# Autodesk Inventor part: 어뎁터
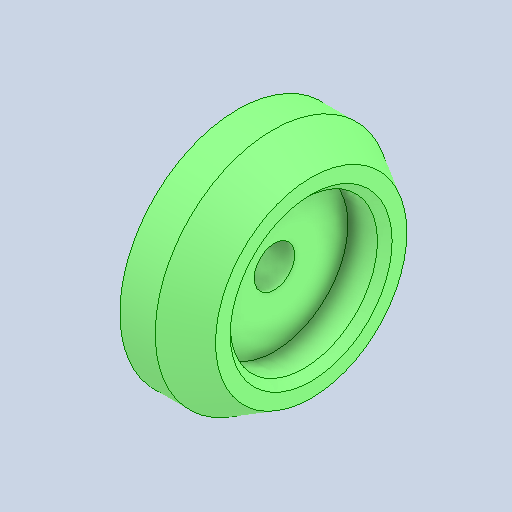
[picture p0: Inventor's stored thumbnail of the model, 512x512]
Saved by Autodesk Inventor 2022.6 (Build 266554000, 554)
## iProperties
Created: 2024-09
Part Number: 어뎁터
Material: 강철, 탄소
Document SubType Name: Modeling
Designer: Class 001
Density: 7.85 g/cm^3
Appearance: 기본값
Author: jhkim
Sending System: Autodesk Inventor 2025
Preprocessor: ST-DEVELOPER v20
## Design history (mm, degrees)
feature "솔리드1"
node "솔리드2"
